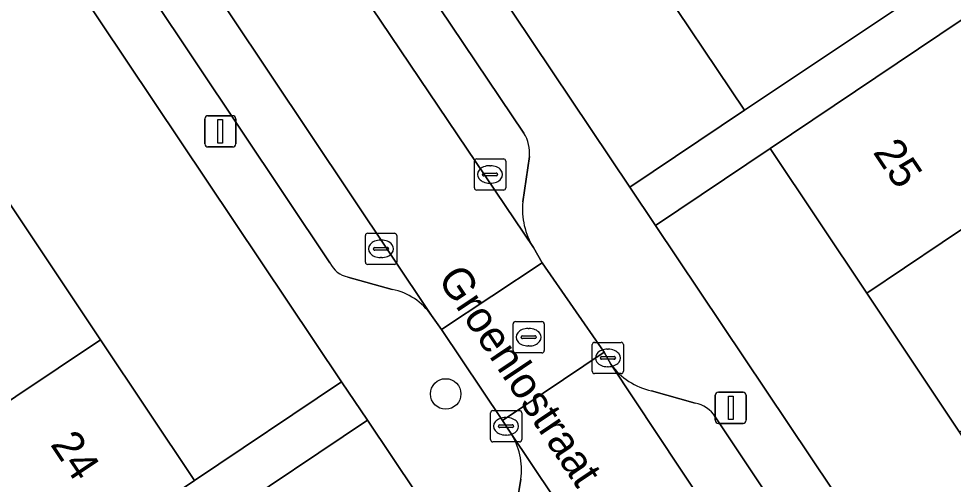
# Model space of a CAD drawing. Extents: x 158352 to 159489, y 383828 to 384603.
# Drawn here: x 158776.65 to 158806.57, y 384347.71 to 384362.44 of the extents above; entities that cross this region are included whole.
import ezdxf

# ---------------------------------------------------------------- set-up
doc = ezdxf.new("R2010")
doc.units = 0
for name, color, linetype in [('IMGEO_Boom', 7, 'Continuous'), ('IMGEO_Erf', 7, 'Continuous'), ('IMGEO_Kolk', 7, 'Continuous'), ('IMGEO_Lichtmast', 7, 'Continuous'), ('IMGEO_Openbare_ruimte_label', 7, 'Continuous'), ('IMGEO_Pand', 7, 'Continuous'), ('IMGEO_Pand_nummerreeks', 7, 'Continuous'), ('IMGEO_Parkeervlak_open', 7, 'Continuous'), ('IMGEO_Rijbaan_lokaal_open', 7, 'Continuous'), ('IMGEO_Rioolput', 7, 'Continuous'), ('IMGEO_Voetpad_open', 7, 'Continuous')]:
    doc.layers.add(name, color=color, linetype=linetype)

msp = doc.modelspace()

# ---------------------------------------------------------------- linework, layer by layer
at = {"layer": 'IMGEO_Boom'}
msp.add_circle((158790.321, 384350.441), 0.489, dxfattribs=at)
at = {"layer": 'IMGEO_Erf'}
for points in [[(158791.304, 384372.289), (158790.934, 384372.839), (158790.862, 384372.946), (158789.856, 384372.274), (158786.777, 384376.873), (158787.052, 384377.056), (158784.24, 384381.244), (158783.966, 384381.06), (158780.817, 384385.769), (158778.153, 384383.982), (158796.216, 384357.055), (158799.886, 384359.517), (158796.844, 384364.044), (158793.86, 384368.484)], [(158768.932, 384377.759), (158765.29, 384375.317), (158768.421, 384370.629), (158768.12, 384370.429), (158770.944, 384366.215), (158771.21, 384366.393), (158774.349, 384361.704), (158773.343, 384361.031), (158776.32, 384356.584), (158779.269, 384352.177), (158782.283, 384347.674), (158786.99, 384350.831)], [(158809.208, 384345.578), (158806.773, 384349.222), (158803.801, 384353.669), (158800.712, 384358.292), (158797.039, 384355.828), (158814.765, 384329.403), (158817.406, 384331.174), (158814.613, 384335.344), (158814.887, 384335.528), (158814.379, 384336.285), (158812.564, 384338.988), (158811.976, 384339.864), (158811.702, 384339.68), (158808.701, 384344.158), (158809.706, 384344.833), (158809.603, 384344.987)], [(158787.815, 384349.601), (158783.109, 384346.446), (158786.094, 384341.995), (158789.06, 384337.574), (158792.045, 384333.123), (158793.05, 384333.798), (158796.193, 384329.112), (158795.928, 384328.925), (158798.729, 384324.728), (158799.003, 384324.912), (158802.155, 384320.22), (158805.854, 384322.701), (158805.841, 384322.72)]]:
    msp.add_lwpolyline(points, close=True, dxfattribs=at)
at = {"layer": 'IMGEO_Kolk'}
for p, q in [((158791.241, 384357.034), (158791.241, 384357.886)), ((158791.316, 384357.96), (158792.168, 384357.96)), ((158791.729, 384357.74), (158791.754, 384357.74)), ((158792.242, 384357.886), (158792.242, 384357.034)), ((158791.5, 384357.454), (158791.5, 384357.466)), ((158791.938, 384357.417), (158791.54, 384357.417)), ((158791.543, 384357.503), (158791.941, 384357.503)), ((158791.984, 384357.466), (158791.984, 384357.454)), ((158791.752, 384357.18), (158791.727, 384357.18)), ((158792.168, 384356.96), (158791.316, 384356.96)), ((158787.751, 384354.655), (158787.751, 384355.507)), ((158787.826, 384355.581), (158788.678, 384355.581)), ((158788.239, 384355.361), (158788.264, 384355.361)), ((158788.752, 384355.507), (158788.752, 384354.655)), ((158788.01, 384355.075), (158788.01, 384355.087)), ((158788.448, 384355.038), (158788.05, 384355.038)), ((158788.053, 384355.124), (158788.451, 384355.124)), ((158788.494, 384355.087), (158788.494, 384355.075)), ((158788.262, 384354.801), (158788.237, 384354.801)), ((158788.678, 384354.581), (158787.826, 384354.581)), ((158795.013, 384351.166), (158795.013, 384352.018)), ((158795.088, 384352.092), (158795.94, 384352.092)), ((158796.014, 384352.018), (158796.014, 384351.166)), ((158795.501, 384351.872), (158795.526, 384351.872)), ((158795.272, 384351.586), (158795.272, 384351.598)), ((158795.71, 384351.549), (158795.312, 384351.549)), ((158795.315, 384351.635), (158795.713, 384351.635)), ((158795.756, 384351.598), (158795.756, 384351.586)), ((158795.524, 384351.312), (158795.499, 384351.312)), ((158795.94, 384351.092), (158795.088, 384351.092)), ((158791.829, 384349.908), (158792.681, 384349.908)), ((158791.754, 384348.982), (158791.754, 384349.834)), ((158792.242, 384349.688), (158792.267, 384349.688)), ((158792.755, 384349.834), (158792.755, 384348.982)), ((158792.013, 384349.402), (158792.013, 384349.414)), ((158792.451, 384349.365), (158792.053, 384349.365)), ((158792.056, 384349.451), (158792.454, 384349.451)), ((158792.497, 384349.414), (158792.497, 384349.402)), ((158792.265, 384349.128), (158792.24, 384349.128)), ((158792.681, 384348.908), (158791.829, 384348.908))]:
    msp.add_line(p, q, dxfattribs=at)
for points in [[(158791.241, 384357.034), (158791.241, 384357.886)], [(158791.316, 384357.96), (158792.168, 384357.96)], [(158792.242, 384357.886), (158792.242, 384357.034)], [(158792.168, 384356.96), (158791.316, 384356.96)], [(158787.751, 384354.655), (158787.751, 384355.507)], [(158787.826, 384355.581), (158788.678, 384355.581)], [(158788.752, 384355.507), (158788.752, 384354.655)], [(158788.678, 384354.581), (158787.826, 384354.581)], [(158795.013, 384351.166), (158795.013, 384352.018)], [(158795.088, 384352.092), (158795.94, 384352.092)], [(158796.014, 384352.018), (158796.014, 384351.166)], [(158795.94, 384351.092), (158795.088, 384351.092)], [(158791.829, 384349.908), (158792.681, 384349.908)], [(158791.754, 384348.982), (158791.754, 384349.834)], [(158792.755, 384349.834), (158792.755, 384348.982)], [(158792.681, 384348.908), (158791.829, 384348.908)]]:
    msp.add_lwpolyline(points, dxfattribs=at)
for centre, radius, start, end in [((158791.318, 384357.884), 0.0765, 91.552, 178.448), ((158791.318, 384357.884), 0.0765, 91.552, 178.448), ((158792.166, 384357.884), 0.0765, 1.552, 88.448), ((158792.166, 384357.884), 0.0765, 1.552, 88.448), ((158791.54, 384357.463), 0.0403, 85.8775, 175.7526), ((158791.537, 384357.453), 0.0366, 178.938, 274.7102), ((158791.941, 384357.46), 0.043, 264.8664, 352.4533), ((158791.945, 384357.465), 0.0386, 1.7309, 96.639), ((158791.318, 384357.036), 0.0765, 181.552, 268.448), ((158791.318, 384357.036), 0.0765, 181.552, 268.448), ((158792.166, 384357.036), 0.0765, 271.552, 358.448), ((158792.166, 384357.036), 0.0765, 271.552, 358.448), ((158787.828, 384355.505), 0.0765, 91.552, 178.448), ((158787.828, 384355.505), 0.0765, 91.552, 178.448), ((158788.676, 384355.505), 0.0765, 1.552, 88.448), ((158788.676, 384355.505), 0.0765, 1.552, 88.448), ((158788.05, 384355.084), 0.0403, 85.8775, 175.7526), ((158788.047, 384355.074), 0.0366, 178.938, 274.7102), ((158788.451, 384355.081), 0.043, 264.8664, 352.4533), ((158788.455, 384355.086), 0.0386, 1.7309, 96.639), ((158787.828, 384354.657), 0.0765, 181.552, 268.448), ((158787.828, 384354.657), 0.0765, 181.552, 268.448), ((158788.676, 384354.657), 0.0765, 271.552, 358.448), ((158788.676, 384354.657), 0.0765, 271.552, 358.448), ((158795.09, 384352.016), 0.0765, 91.552, 178.448), ((158795.09, 384352.016), 0.0765, 91.552, 178.448), ((158795.938, 384352.016), 0.0765, 1.552, 88.448), ((158795.938, 384352.016), 0.0765, 1.552, 88.448), ((158795.312, 384351.595), 0.0403, 85.8775, 175.7526), ((158795.309, 384351.585), 0.0366, 178.938, 274.7102), ((158795.713, 384351.592), 0.043, 264.8664, 352.4533), ((158795.717, 384351.597), 0.0386, 1.7309, 96.639), ((158795.09, 384351.168), 0.0765, 181.552, 268.448), ((158795.09, 384351.168), 0.0765, 181.552, 268.448), ((158795.938, 384351.168), 0.0765, 271.552, 358.448), ((158795.938, 384351.168), 0.0765, 271.552, 358.448), ((158791.831, 384349.832), 0.0765, 91.552, 178.448), ((158791.831, 384349.832), 0.0765, 91.552, 178.448), ((158792.679, 384349.832), 0.0765, 1.552, 88.448), ((158792.679, 384349.832), 0.0765, 1.552, 88.448), ((158792.053, 384349.411), 0.0403, 85.8775, 175.7526), ((158792.05, 384349.401), 0.0366, 178.938, 274.7102), ((158792.454, 384349.408), 0.043, 264.8664, 352.4533), ((158792.458, 384349.413), 0.0386, 1.7309, 96.639), ((158791.831, 384348.984), 0.0765, 181.552, 268.448), ((158791.831, 384348.984), 0.0765, 181.552, 268.448), ((158792.679, 384348.984), 0.0765, 271.552, 358.448), ((158792.679, 384348.984), 0.0765, 271.552, 358.448)]:
    msp.add_arc(centre, radius, start, end, dxfattribs=at)
for centre, major_axis, ratio, start_param, end_param in [((158791.728, 384357.46), (-0.387, 0.002), 0.722429, 4.712389, 7.853982), ((158791.753, 384357.46), (-0.39, 0.002), 0.717154, 1.570796, 4.712389), ((158788.238, 384355.081), (-0.387, 0.002), 0.722429, 4.712389, 7.853982), ((158788.263, 384355.081), (-0.39, 0.002), 0.717154, 1.570796, 4.712389), ((158795.5, 384351.592), (-0.387, 0.002), 0.722429, 4.712389, 7.853982), ((158795.525, 384351.592), (-0.39, 0.002), 0.717154, 1.570796, 4.712389), ((158792.241, 384349.408), (-0.387, 0.002), 0.722429, 4.712389, 7.853982), ((158792.266, 384349.408), (-0.39, 0.002), 0.717154, 1.570796, 4.712389)]:
    msp.add_ellipse(centre, major_axis=major_axis, ratio=ratio, start_param=start_param, end_param=end_param, dxfattribs=at)
at = {"layer": 'IMGEO_Lichtmast'}
for p, q in [((158782.608, 384358.438), (158782.608, 384359.238)), ((158782.608, 384359.238), (158782.608, 384358.438)), ((158782.708, 384359.338), (158783.498, 384359.338)), ((158783.498, 384359.338), (158782.708, 384359.338)), ((158783.598, 384359.238), (158783.598, 384358.438)), ((158783.598, 384358.438), (158783.598, 384359.238)), ((158783.498, 384358.338), (158782.708, 384358.338)), ((158782.708, 384358.338), (158783.498, 384358.338)), ((158798.951, 384349.599), (158798.951, 384350.399)), ((158798.951, 384350.399), (158798.951, 384349.599)), ((158799.051, 384350.499), (158799.841, 384350.499)), ((158799.841, 384350.499), (158799.051, 384350.499)), ((158799.941, 384350.399), (158799.941, 384349.599)), ((158799.941, 384349.599), (158799.941, 384350.399)), ((158799.841, 384349.499), (158799.051, 384349.499)), ((158799.051, 384349.499), (158799.841, 384349.499))]:
    msp.add_line(p, q, dxfattribs=at)
for points in [[(158783.028, 384359.213), (158783.178, 384359.213), (158783.178, 384358.463), (158783.028, 384358.463), (158783.028, 384359.213)], [(158799.371, 384350.374), (158799.521, 384350.374), (158799.521, 384349.624), (158799.371, 384349.624), (158799.371, 384350.374)]]:
    msp.add_lwpolyline(points, dxfattribs=at)
for centre, start, end in [((158782.708, 384359.238), 90, 180), ((158782.708, 384359.238), 90, 180), ((158783.498, 384359.238), 0, 90), ((158783.498, 384359.238), 360, 90), ((158782.708, 384358.438), 180, 270), ((158782.708, 384358.438), 180, 270), ((158783.498, 384358.438), 270, 0), ((158783.498, 384358.438), 270, 0), ((158799.051, 384350.399), 90, 180), ((158799.051, 384350.399), 90, 180), ((158799.841, 384350.399), 0, 90), ((158799.841, 384350.399), 360, 90), ((158799.051, 384349.599), 180, 270), ((158799.051, 384349.599), 180, 270), ((158799.841, 384349.599), 270, 0), ((158799.841, 384349.599), 270, 0)]:
    msp.add_arc(centre, 0.1, start, end, dxfattribs=at)
at = {"layer": 'IMGEO_Pand'}
for points in [[(158806.371, 384370.408), (158796.844, 384364.044), (158799.886, 384359.517), (158805.842, 384363.496), (158804.4, 384365.655), (158807.958, 384368.033)], [(158813.447, 384360.142), (158816.058, 384361.91), (158814.533, 384364.237), (158811.889, 384362.464), (158811.842, 384362.534), (158808.312, 384360.165), (158806.819, 384362.39), (158800.712, 384358.292), (158803.801, 384353.669)], [(158803.801, 384353.669), (158806.773, 384349.222), (158812.896, 384353.331), (158811.52, 384355.381), (158815.052, 384357.751), (158813.447, 384360.142)], [(158770.284, 384352.55), (158771.665, 384350.482), (158768.208, 384348.173), (158769.772, 384345.831), (158779.269, 384352.177), (158776.32, 384356.584)], [(158779.269, 384352.177), (158769.772, 384345.831), (158771.336, 384343.489), (158774.808, 384345.808), (158776.252, 384343.646), (158782.283, 384347.674)]]:
    msp.add_lwpolyline(points, close=True, dxfattribs=at)
at = {"layer": 'IMGEO_Parkeervlak_open'}
for points in [[(158789.868, 384352.95), (158770.492, 384381.895)], [(158770.771, 384378.301), (158786.613, 384354.629)], [(158783.374, 384369.574), (158793.133, 384355.121)], [(158792.828, 384358.785), (158786.653, 384367.946)], [(158792.79, 384356.583), (158793, 384358.031)], [(158787.192, 384354.181), (158788.611, 384353.784)], [(158795.613, 384351.389), (158805.266, 384336.856)], [(158798.304, 384350.148), (158796.912, 384350.539)], [(158805.072, 384340.548), (158798.953, 384349.71)], [(158808.448, 384325.282), (158792.39, 384349.215)], [(158792.73, 384347.713), (158792.491, 384346.268), (158792.714, 384345.518), (158805.215, 384326.905)]]:
    msp.add_lwpolyline(points, dxfattribs=at)
for centre, radius, start, end in [((158791.798, 384358.153), 1.208, 354.1813, 31.5192), ((158795.063, 384356.345), 2.285, 174.0238, 212.383), ((158787.362, 384354.999), 0.835, 206.2697, 258.2686), ((158788.214, 384351.822), 2.002, 34.299, 78.5737), ((158797.373, 384352.662), 2.172, 215.8674, 257.7351), ((158798.122, 384349.178), 0.987, 32.6088, 79.3616), ((158790.521, 384348.003), 2.228, 352.5319, 32.9777)]:
    msp.add_arc(centre, radius, start, end, dxfattribs=at)
at = {"layer": 'IMGEO_Rijbaan_lokaal_open'}
for points in [[(158773.69, 384384.135), (158771.443, 384387.465), (158771.337, 384387.624), (158761.533, 384402.286), (158761.17, 384402.825), (158757.913, 384400.628), (158758.257, 384400.06), (158768.222, 384385.318), (158770.492, 384381.895), (158789.868, 384352.95), (158790.184, 384352.504), (158793.409, 384354.636), (158793.133, 384355.121), (158783.374, 384369.574)], [(158790.184, 384352.504), (158792.145, 384349.596), (158795.391, 384351.773), (158793.409, 384354.636)], [(158812.331, 384326.54), (158811.777, 384327.369), (158805.266, 384336.856), (158795.613, 384351.389), (158795.391, 384351.773), (158792.145, 384349.596), (158792.39, 384349.215), (158808.448, 384325.282), (158810.734, 384321.892), (158810.808, 384321.782), (158824.147, 384301.902), (158827.398, 384304.097), (158815.814, 384321.331), (158815.256, 384322.165)]]:
    msp.add_lwpolyline(points, close=True, dxfattribs=at)
at = {"layer": 'IMGEO_Rioolput'}
for p, q in [((158792.476, 384351.829), (158792.476, 384352.681)), ((158792.551, 384352.755), (158793.403, 384352.755)), ((158793.477, 384352.681), (158793.477, 384351.829)), ((158792.964, 384352.535), (158792.989, 384352.535)), ((158792.735, 384352.249), (158792.735, 384352.261)), ((158793.173, 384352.212), (158792.775, 384352.212)), ((158792.778, 384352.298), (158793.176, 384352.298)), ((158793.219, 384352.261), (158793.219, 384352.249)), ((158793.403, 384351.755), (158792.551, 384351.755)), ((158792.987, 384351.975), (158792.962, 384351.975))]:
    msp.add_line(p, q, dxfattribs=at)
for points in [[(158792.476, 384351.829), (158792.476, 384352.681)], [(158792.551, 384352.755), (158793.403, 384352.755)], [(158793.477, 384352.681), (158793.477, 384351.829)], [(158793.403, 384351.755), (158792.551, 384351.755)]]:
    msp.add_lwpolyline(points, dxfattribs=at)
for centre, radius, start, end in [((158792.553, 384352.679), 0.0765, 91.552, 178.448), ((158792.553, 384352.679), 0.0765, 91.552, 178.448), ((158793.401, 384352.679), 0.0765, 1.552, 88.448), ((158793.401, 384352.679), 0.0765, 1.552, 88.448), ((158792.775, 384352.258), 0.0403, 85.8775, 175.7526), ((158792.772, 384352.248), 0.0366, 178.938, 274.7102), ((158793.176, 384352.255), 0.043, 264.8664, 352.4533), ((158793.18, 384352.26), 0.0386, 1.7309, 96.639), ((158792.553, 384351.831), 0.0765, 181.552, 268.448), ((158792.553, 384351.831), 0.0765, 181.552, 268.448), ((158793.401, 384351.831), 0.0765, 271.552, 358.448), ((158793.401, 384351.831), 0.0765, 271.552, 358.448)]:
    msp.add_arc(centre, radius, start, end, dxfattribs=at)
for centre, major_axis, ratio, start_param, end_param in [((158792.963, 384352.255), (-0.387, 0.002), 0.722429, 4.712389, 7.853982), ((158792.988, 384352.255), (-0.39, 0.002), 0.717154, 1.570796, 4.712389)]:
    msp.add_ellipse(centre, major_axis=major_axis, ratio=ratio, start_param=start_param, end_param=end_param, dxfattribs=at)
at = {"layer": 'IMGEO_Voetpad_open'}
for points in [[(158797.039, 384355.828), (158796.216, 384357.055), (158778.153, 384383.982), (158777.224, 384385.366), (158762.382, 384407.492), (158759.629, 384408.116)], [(158753.504, 384404.062), (158753.174, 384401.294), (158759.532, 384391.777), (158767.955, 384379.216), (158768.932, 384377.759), (158786.99, 384350.831), (158787.815, 384349.601), (158805.841, 384322.72), (158805.854, 384322.701), (158806.635, 384321.537), (158806.727, 384321.4), (158822.323, 384298.139), (158824.974, 384299.926)], [(158786.613, 384354.629), (158770.771, 384378.301)], [(158818.889, 384372.181), (158805.842, 384363.496), (158799.886, 384359.517), (158796.216, 384357.055), (158797.039, 384355.828), (158800.712, 384358.292), (158806.819, 384362.39)], [(158786.653, 384367.946), (158792.828, 384358.785)], [(158793, 384358.031), (158792.79, 384356.583)], [(158828.93, 384302.592), (158831.561, 384304.365), (158815.887, 384327.73), (158814.765, 384329.403), (158797.039, 384355.828)], [(158793.133, 384355.121), (158793.409, 384354.636), (158795.391, 384351.773), (158795.613, 384351.389)], [(158788.611, 384353.784), (158787.192, 384354.181)], [(158792.39, 384349.215), (158792.145, 384349.596), (158790.184, 384352.504), (158789.868, 384352.95)], [(158777.138, 384342.418), (158783.109, 384346.446), (158787.815, 384349.601), (158786.99, 384350.831), (158782.283, 384347.674), (158776.252, 384343.646), (158763.113, 384334.884), (158756.206, 384345.242)], [(158796.912, 384350.539), (158798.304, 384350.148)], [(158798.953, 384349.71), (158805.072, 384340.548)], [(158805.215, 384326.905), (158792.714, 384345.518), (158792.491, 384346.268), (158792.73, 384347.713)]]:
    msp.add_lwpolyline(points, dxfattribs=at)
for centre, radius, start, end in [((158791.798, 384358.153), 1.208, 354.1813, 31.5192), ((158795.063, 384356.345), 2.285, 174.0238, 212.383), ((158787.362, 384354.999), 0.835, 206.2697, 258.2686), ((158788.214, 384351.822), 2.002, 34.299, 78.5737), ((158797.373, 384352.662), 2.172, 215.8674, 257.7351), ((158798.122, 384349.178), 0.987, 32.6088, 79.3616), ((158790.521, 384348.003), 2.228, 352.5319, 32.9777)]:
    msp.add_arc(centre, radius, start, end, dxfattribs=at)

# ---------------------------------------------------------------- texts
at = {"layer": 'IMGEO_Openbare_ruimte_label'}
msp.add_text('Groenlostraat', height=1, rotation=303.7854, dxfattribs=at).set_placement((158790.041, 384354.123))
at = {"layer": 'IMGEO_Pand_nummerreeks'}
for s, rotation, p in [('25', 303.8616, (158803.979, 384358.172)), ('24', 303.7348, (158777.644, 384348.828))]:
    msp.add_text(s, height=1, rotation=rotation, dxfattribs=at).set_placement(p)

doc.saveas('drawing.dxf')
